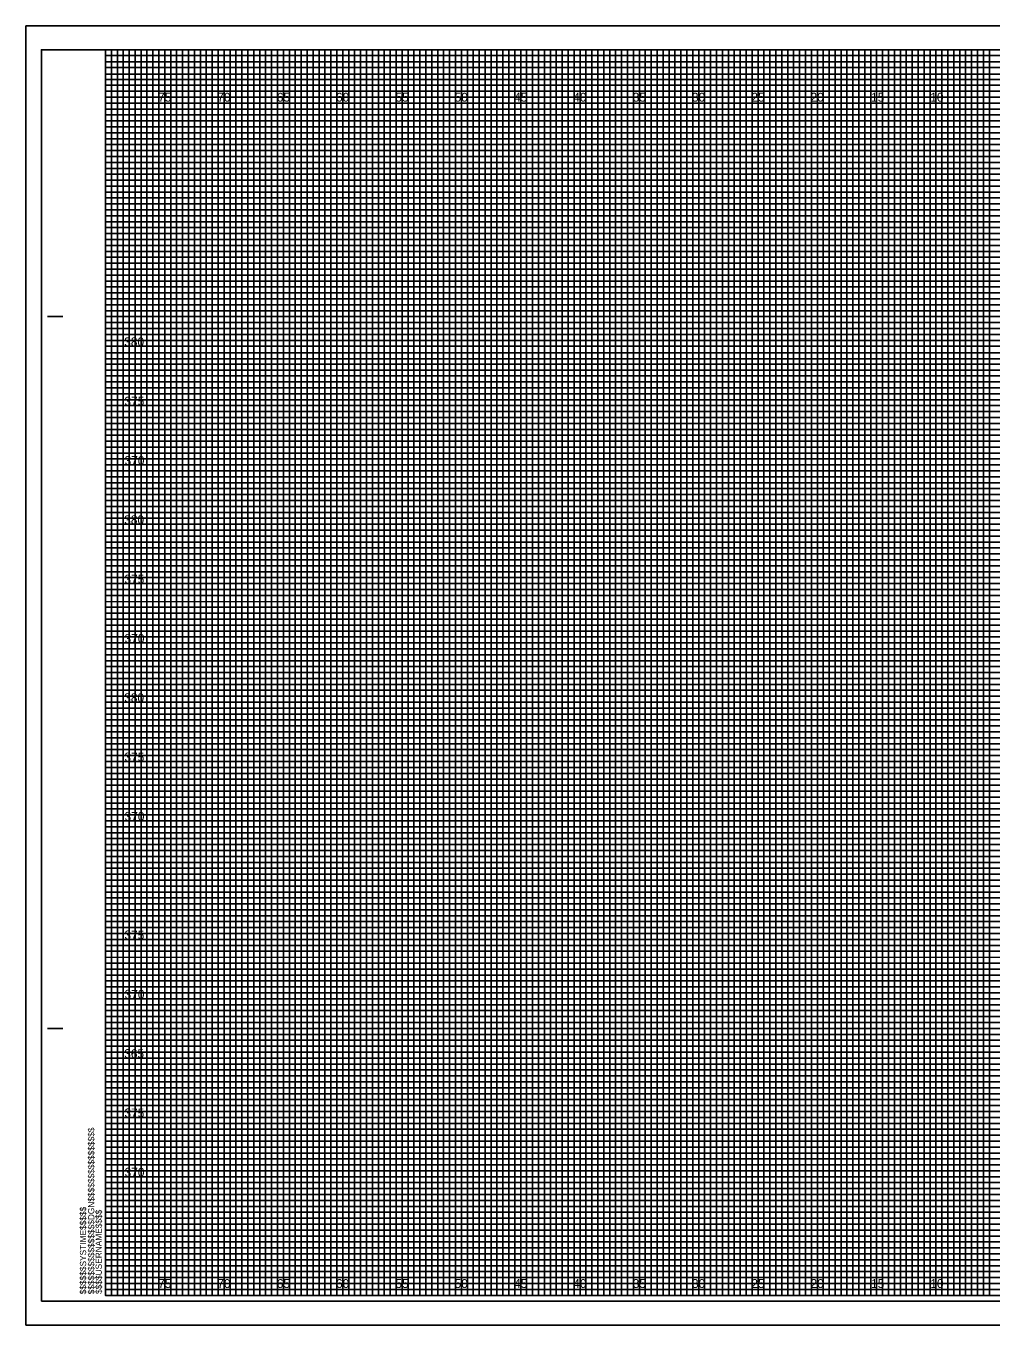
# Model space of a CAD drawing. Extents: x -7 to 162, y -2 to 327.
# Drawn here: x -6.7 to 74.6, y 107.5 to 217 of the extents above; entities that cross this region are included whole.
import ezdxf

# ---------------------------------------------------------------- set-up
doc = ezdxf.new("R2010")
doc.units = 0
for name, color, linetype in [('Exist Cross Section Cell', 7, 'Continuous'), ('Prop CMT Pvmt Course 1', 7, 'Continuous'), ('Prop CMT Pvmt Course 3', 7, 'Continuous'), ('Prop CMT Shld Paved Course 1', 7, 'Continuous'), ('Prop CMT Shld Paved Course 2', 7, 'Continuous'), ('Prop CMT Shld Paved Course 3', 7, 'Continuous'), ('Prop CMT Slope Grass', 7, 'Continuous'), ('Prop CMT Subgrade Earthwork', 7, 'Continuous'), ('Scratch_Level_3', 7, 'Continuous')]:
    doc.layers.add(name, color=color, linetype=linetype)

msp = doc.modelspace()

# ---------------------------------------------------------------- linework, layer by layer
at = {"layer": 'Prop CMT Pvmt Course 3'}
msp.add_lwpolyline([(-6.7, 107.5), (161.65, 107.5), (161.65, 217), (-6.7, 217)], close=True, dxfattribs=at)
at = {"layer": 'Prop CMT Shld Paved Course 1'}
for p, q in [((0, 214.5), (110.95, 214.5)), ((110.95, 213.99), (0, 213.99)), ((0, 213.99), (0, 213.5)), ((0, 213.5), (110.95, 213.5)), ((110.95, 212.94), (0, 212.94)), ((0, 212.94), (0, 212)), ((0, 212), (160, 212))]:
    msp.add_line(p, q, dxfattribs=at)
for points in [[(0, 211.5), (135, 211.5), (160, 211.5)], [(160, 211), (0, 211)], [(0, 210.5), (160, 210.5)], [(160, 209.5), (0, 209.5)], [(0, 209), (160, 209)], [(160, 208.5), (0, 208.49)], [(0, 208), (160, 208)], [(160, 207), (0, 207)], [(0, 206.5), (160, 206.5), (160, 206), (0, 206)], [(0, 205.5), (160, 205.5), (160, 204.5), (0, 204.5)], [(0, 204), (160, 204), (160, 203.5), (0, 203.5)], [(0, 203), (160, 203), (160, 202), (0, 202)], [(0, 201.5), (160, 201.5), (160, 201), (0, 201)], [(0, 200.5), (160, 200.5), (160, 199.5), (0, 199.5)], [(0, 199), (160, 199), (160, 198.5), (0, 198.5)], [(0, 198), (160, 198), (160, 196.97), (160, 196.5), (160, 196), (0, 196)], [(0, 197), (160, 197), (160, 196.5), (0, 196.5)], [(0, 195.5), (160, 195.5), (160, 194.5), (0, 194.51)], [(0, 194.51), (160, 194.5), (160, 194), (0, 194)], [(0, 193.5), (160, 193.5), (160, 193), (0, 193)], [(0, 192), (160, 192), (160, 191.5), (0, 191.5)], [(0, 191), (160, 191), (160, 190.5), (0, 190.5)], [(-0.04, 189.44), (160, 189.44), (160, 188.94), (-0.04, 188.94)], [(0, 188.5), (160, 188.5), (160, 188), (0, 188)], [(0, 187), (160, 187), (160, 186.5), (0, 186.5)], [(0, 186), (160, 186), (160, 185.5), (0, 185.5)], [(0, 184.5), (160, 184.5), (160, 184), (0, 184)], [(0, 183.5), (160, 183.5), (160, 183), (0, 183)], [(0, 182), (160, 182), (160, 181.5), (0, 181.5)], [(0, 181), (160, 181), (160, 180.5), (0, 180.5)], [(0, 179.5), (160, 179.5), (159.99, 178.99), (0, 179)], [(0, 178.5), (160, 178.5), (160, 178), (0, 178)], [(0, 177), (160, 177), (160, 176.5), (0, 176.5)], [(0, 176), (160, 176), (160, 175.5), (0, 175.5)], [(0, 174.5), (160, 174.5), (160, 174), (0, 174)], [(0, 173.5), (160, 173.5), (160, 173), (0, 173)], [(0, 172), (160, 172), (160, 171.5), (0, 171.5)], [(0, 171), (160, 171), (160, 170.5), (0, 170.5)], [(0, 169.5), (160, 169.5), (160, 169), (0, 169)], [(0, 168.5), (160.03, 168.45), (160, 168), (0, 168)], [(0, 167), (160, 167), (160, 166.5), (0, 166.5)], [(0, 166), (160, 166), (160, 165.5), (0, 165.5)], [(0, 164.5), (160, 164.5), (160, 164), (0, 164)], [(0, 163.5), (160, 163.5), (160, 163), (0, 163)], [(0, 162), (160, 162), (160, 161.5), (0, 161.5)], [(0, 161), (160, 161), (160, 160.5), (0, 160.5)], [(0, 159.5), (160, 159.5), (160, 159), (0, 159)], [(0, 158.5), (160, 158.5), (160, 158), (0, 158)], [(0, 157), (160, 157), (160, 156.5), (0, 156.5)], [(0, 156), (160, 156), (160, 155.5), (0, 155.5)], [(0, 154.5), (160, 154.5), (160, 154), (0, 154)], [(0, 153.5), (160, 153.5), (160, 153), (0, 153)], [(0, 152), (160, 152), (160, 151.5), (0, 151.5)], [(0, 151), (160, 151), (160, 150.5), (0, 150.5)], [(0, 149.5), (160, 149.5), (159.99, 148.99), (0, 149)], [(0, 148.5), (160, 148.5), (160, 148), (0, 148)], [(0, 147), (160, 147), (160, 146.5), (0, 146.5)], [(0, 146), (160, 146), (160, 145.5), (0, 145.5)], [(0, 144.5), (160, 144.5), (160, 144), (0, 144)], [(0, 143.5), (160, 143.5), (160, 143), (0, 143)], [(0, 142), (160, 142), (160, 141.5), (0, 141.5)], [(0, 141), (160, 141), (160, 140.5), (0, 140.5)], [(0, 139.5), (160, 139.5), (160, 139), (0, 139)], [(0, 138.5), (160.03, 138.46), (160, 138), (0, 138)], [(0, 137), (160, 137), (160, 136.5), (0, 136.5)], [(0, 136), (160, 136), (160, 135.5), (0, 135.5)], [(0, 134.5), (160, 134.5), (160, 134), (0, 134)], [(0, 133.5), (160, 133.5), (160, 133), (0, 133)], [(0, 132), (160, 132), (160, 131.5), (0, 131.5)], [(0, 131), (160, 131), (160, 130.5), (0, 130.5)], [(0, 129.5), (160, 129.5), (160, 129), (0, 129)], [(0, 128.5), (160, 128.5), (160, 128), (0, 128)], [(0, 127), (160, 127), (160, 126.5), (0, 126.5)], [(0, 126), (160, 126), (160, 125.5), (0, 125.5)], [(0, 124.5), (160, 124.5), (160, 124), (0, 124)], [(0, 123.5), (160, 123.5), (160, 123), (0, 123)], [(0, 122), (160, 122), (160, 121.5), (0, 121.5)], [(0, 121), (160, 121), (160, 120.5), (0, 120.5)], [(0, 119.5), (160, 119.5), (160, 119), (0, 119)], [(0, 118.5), (160, 118.5), (160, 118), (0, 118)], [(0, 117), (160, 117), (160, 116.5), (0, 116.5)], [(0, 116), (160, 116), (160, 115.5), (0, 115.5)], [(0, 114.5), (160, 114.5), (160, 114), (0, 114)], [(0, 113.5), (160, 113.5), (160, 113), (0, 113)], [(0, 112), (160, 112), (160, 111.5), (0, 111.5)], [(0, 111), (160, 111), (160, 110.5), (0, 110.5)]]:
    msp.add_lwpolyline(points, dxfattribs=at)
at = {"layer": 'Prop CMT Shld Paved Course 2'}
for p, q in [((-4.9, 192.5), (-3.65, 192.5)), ((-4.85, 192.5), (-3.6, 192.5)), ((-4.9, 132.5), (-3.65, 132.5)), ((-4.85, 132.5), (-3.6, 132.5)), ((0, 110), (0, 110)), ((0, 110), (0, 110)), ((0, 110), (0, 110)), ((0, 110), (0, 110)), ((0, 110), (0, 110)), ((0, 110), (0, 110)), ((0, 110), (0, 110))]:
    msp.add_line(p, q, dxfattribs=at)
msp.add_lwpolyline([(160, 215), (0, 215), (0, 110), (160, 110)], close=True, dxfattribs=at)
at = {"layer": 'Prop CMT Shld Paved Course 3'}
for points in [[(0, 110), (0.5, 110), (0.5, 215), (1, 215), (1, 110)], [(1, 110), (1.5, 110), (1.5, 215), (2, 215), (2, 110)], [(2.5, 110), (3, 110), (3, 215), (3.5, 215), (3.5, 110)], [(3.5, 110), (4, 110), (4, 215), (4.5, 215), (4.5, 110)], [(5, 110), (5.5, 110), (5.5, 215), (6, 215), (6, 110)], [(6, 110), (6.5, 110), (6.5, 215), (7, 215), (7, 110)], [(7.5, 110), (8, 110), (8, 215), (8.5, 215), (8.5, 110)], [(8.5, 110), (9, 110), (9, 215), (9.5, 215), (9.5, 110)], [(10, 110), (10.5, 110), (10.5, 215), (11, 215), (11, 110)], [(11, 110), (11.5, 110), (11.5, 215), (12, 215), (12, 110)], [(12.5, 110), (13, 110), (13, 215), (13.5, 215), (13.5, 110)], [(13.5, 110), (14, 110), (14, 215), (14.5, 215), (14.5, 110)], [(15, 110), (15.5, 110), (15.5, 215), (16, 215), (16, 110)], [(16, 110), (16.5, 110), (16.5, 215), (17, 215), (17, 110)], [(17.5, 110), (18, 110), (18, 215), (18.5, 215), (18.5, 110)], [(18.5, 110), (19, 110), (19, 215), (19.5, 215), (19.5, 110)], [(20, 110), (20.5, 110), (20.5, 215), (21, 215), (21, 110)], [(21, 110), (21.5, 110), (21.5, 215), (22, 215), (22, 110)], [(22.5, 110), (23, 110), (23, 215), (23.5, 215), (23.5, 110)], [(23.5, 110), (24, 110), (24, 215), (24.5, 215), (24.5, 110)], [(25, 110), (25.5, 110), (25.5, 215), (26, 215), (26, 110)], [(26, 110), (26.5, 110), (26.5, 215), (27, 215), (27, 110)], [(27.5, 110), (28, 110), (28, 215), (28.5, 215), (28.5, 110)], [(28.5, 110), (29, 110), (29, 215), (29.5, 215), (29.5, 110)], [(30, 110), (30.5, 110), (30.5, 215), (31, 215), (31, 110)], [(31, 110), (31.5, 110), (31.5, 215), (32, 215), (32, 110)], [(32.5, 110), (33, 110), (33, 215), (33.5, 215), (33.5, 110)], [(33.5, 110), (34, 110), (34, 215), (34.5, 215), (34.5, 110)], [(35, 110), (35.5, 110), (35.5, 215), (36, 215), (36, 110)], [(36, 110), (36.5, 110), (36.5, 215), (37, 215), (37, 110)], [(37.5, 110), (38, 110), (38, 215), (38.5, 215), (38.5, 110)], [(38.5, 110), (39, 110), (39, 215), (39.5, 215), (39.5, 110)], [(40, 110), (40.5, 110), (40.5, 215), (41, 215), (41, 110)], [(41, 110), (41.5, 110), (41.5, 215), (42, 215), (42, 110)], [(42.5, 110), (43, 110), (43, 215), (43.5, 215), (43.5, 110)], [(43.5, 110), (44, 110), (44, 215), (44.5, 215), (44.5, 110)], [(45, 110), (45.5, 110), (45.5, 215), (46, 215), (46, 110)], [(46, 110), (46.5, 110), (46.5, 215), (47, 215), (47, 110)], [(47.5, 110), (48, 110), (48, 215), (48.5, 215), (48.5, 110)], [(48.5, 110), (49, 110), (49, 215), (49.5, 215), (49.5, 110)], [(50, 110), (50.5, 110), (50.5, 215), (51, 215), (51, 110)], [(51, 110), (51.5, 110), (51.5, 215), (52, 215), (52, 110)], [(52.5, 110), (53, 110), (53, 215), (53.5, 215), (53.5, 110)], [(53.5, 110), (54, 110), (54, 215), (54.5, 215), (54.5, 110)], [(55, 110), (55.5, 110), (55.5, 215), (56, 215), (56, 110)], [(56, 110), (56.5, 110), (56.5, 215), (57, 215), (57, 110)], [(57.5, 110), (58, 110), (58, 215), (58.5, 215), (58.5, 110)], [(58.5, 110), (59, 110), (59, 215), (59.5, 215), (59.5, 110)], [(60, 110), (60.5, 110), (60.5, 215), (61, 215), (61, 110)], [(61, 110), (61.5, 110), (61.5, 215), (62, 215), (62, 110)], [(62.5, 110), (63, 110), (63, 215), (63.5, 215), (63.5, 110)], [(63.5, 110), (64, 110), (64, 215), (64.5, 215), (64.5, 110)], [(65, 110), (65.5, 110), (65.5, 215), (66, 215), (66, 110)], [(66, 110), (66.5, 110), (66.5, 215), (67, 215), (67, 110)], [(67.5, 110), (68, 110), (68, 215), (68.5, 215), (68.5, 110)], [(68.5, 110), (69, 110), (69, 215), (69.5, 215), (69.5, 110)], [(70, 110), (70.5, 110), (70.5, 215), (71, 215), (71, 110)], [(71, 110), (71.5, 110), (71.5, 215), (72, 215), (72, 110)], [(72.5, 110), (73, 110), (73, 215), (73.5, 215), (73.5, 110)], [(73.5, 110), (74, 110), (74, 215), (74.5, 215), (74.5, 110)]]:
    msp.add_lwpolyline(points, dxfattribs=at)
at = {"layer": 'Prop CMT Slope Grass'}
for points in [[(0, 215), (2.5, 215), (2.5, 110), (7.5, 110), (7.5, 215), (12.5, 215), (12.5, 110), (17.5, 110), (17.5, 215), (22.5, 215), (22.5, 110), (27.5, 110), (27.5, 215), (32.5, 215), (32.5, 110), (37.5, 110), (37.5, 215), (42.5, 215), (42.5, 110), (47.5, 110), (47.5, 215), (52.5, 215), (52.5, 110), (57.5, 110), (57.5, 215), (62.5, 215), (62.5, 110), (67.5, 110), (67.5, 215), (72.5, 215), (72.5, 110), (77.5, 110)], [(0, 212.5), (137.5, 212.5)], [(0, 202.5), (160, 202.5), (160, 212.5)], [(160, 207.5), (0, 207.5)], [(0, 192.5), (160, 192.5), (160, 197.5), (0, 197.5)], [(0, 182.5), (160, 182.5), (160, 187.5), (0, 187.5)], [(0, 172.5), (160, 172.5), (160, 177.5), (0, 177.5)], [(0, 162.5), (160, 162.5), (160, 167.5), (0, 167.5)], [(0, 152.5), (160, 152.5), (160, 157.5), (0, 157.5)], [(0, 142.5), (160, 142.5), (160, 147.5), (0, 147.5)], [(0, 132.5), (160, 132.5), (160, 137.5), (0, 137.5)], [(0, 122.5), (160, 122.5), (160, 127.5), (0, 127.5)], [(0, 112.5), (160, 112.5), (160, 117.5), (0, 117.5)]]:
    msp.add_lwpolyline(points, dxfattribs=at)
at = {"layer": 'Prop CMT Subgrade Earthwork'}
msp.add_lwpolyline([(-5.4, 109.5), (161.2, 109.5), (161.2, 215), (-5.4, 215)], close=True, dxfattribs=at)
at = {"layer": 'Scratch_Level_3'}
for p, q in [((5, 215), (0, 215)), ((5, 110), (5, 215)), ((15, 215), (10, 215)), ((10, 215), (10, 110)), ((15, 110), (15, 215)), ((25, 215), (20, 215)), ((20, 215), (20, 110)), ((25, 110), (25, 215)), ((35, 215), (30, 215)), ((30, 215), (30, 110)), ((35, 110), (35, 215)), ((45, 215), (40, 215)), ((40, 215), (40, 110)), ((45, 110), (45, 215)), ((55, 215), (50, 215)), ((50, 215), (50, 110)), ((55, 110), (55, 215)), ((65, 215), (60, 215)), ((60, 215), (60, 110)), ((65, 110), (65, 215)), ((75, 215), (70, 215)), ((70, 215), (70, 110)), ((10, 110), (5, 110)), ((20, 110), (15, 110)), ((30, 110), (25, 110)), ((40, 110), (35, 110)), ((50, 110), (45, 110)), ((60, 110), (55, 110)), ((70, 110), (65, 110))]:
    msp.add_line(p, q, dxfattribs=at)
for points in [[(160, 212.5), (160, 205), (0, 205)], [(0, 210), (160, 210)], [(0, 200), (160, 200), (160, 195), (0, 195)], [(0, 190), (160, 190), (160, 185), (0, 185)], [(0, 180), (160, 180), (160, 175), (0, 175)], [(0, 170), (160, 170), (160, 165), (0, 165)], [(0, 160), (160, 160), (160, 155), (0, 155)], [(0, 150), (160, 150), (160, 145), (0, 145)], [(0, 140), (160, 140), (160, 135), (0, 135)], [(0, 130), (160, 130), (160, 125), (0, 125)], [(0, 120), (160, 120), (160, 115), (0, 115)]]:
    msp.add_lwpolyline(points, dxfattribs=at)

# ---------------------------------------------------------------- texts
at = {"layer": 'Exist Cross Section Cell'}
for s, p in [('75', (4.44, 210.62)), ('70', (9.43, 210.62)), ('65', (14.44, 210.62)), ('60', (19.43, 210.62)), ('55', (24.44, 210.62)), ('50', (29.43, 210.62)), ('45', (34.44, 210.62)), ('40', (39.43, 210.62)), ('35', (44.44, 210.62)), ('30', (49.43, 210.62)), ('25', (54.44, 210.62)), ('20', (59.43, 210.62)), ('15', (64.53, 210.62)), ('10', (69.52, 210.62)), ('75', (4.44, 110.62)), ('70', (9.43, 110.62)), ('65', (14.44, 110.62)), ('60', (19.43, 110.62)), ('55', (24.44, 110.62)), ('50', (29.43, 110.62)), ('45', (34.44, 110.62)), ('40', (39.43, 110.62)), ('35', (44.44, 110.62)), ('30', (49.43, 110.62)), ('25', (54.44, 110.62)), ('20', (59.43, 110.62)), ('15', (64.53, 110.62)), ('10', (69.52, 110.62))]:
    msp.add_text(s, height=0.75, dxfattribs=at).set_placement(p)
at = {"layer": 'Prop CMT Pvmt Course 1'}
for s, p in [('380', (1.58, 190)), ('375', (1.6, 185)), ('370', (1.61, 180)), ('380', (1.58, 175)), ('375', (1.6, 170)), ('370', (1.61, 165)), ('380', (1.58, 160)), ('375', (1.6, 155)), ('370', (1.61, 150)), ('375', (1.6, 140)), ('370', (1.61, 135)), ('365', (1.58, 130)), ('375', (1.6, 125)), ('370', (1.61, 120))]:
    msp.add_text(s, height=0.75, dxfattribs=at).set_placement(p)
at = {"layer": 'Prop CMT Shld Paved Course 2'}
for s, p in [('$$$$$$$$$$$$$$$$DGN$$$$$$$$$$$$$$$$', (-0.94, 110.09)), ('$$$$$$SYSTIME$$$$$', (-1.63, 110.09)), ('$$$$USERNAME$$$$', (-0.31, 110.12))]:
    msp.add_text(s, height=0.525, rotation=90, dxfattribs=at).set_placement(p)

doc.saveas('drawing.dxf')
